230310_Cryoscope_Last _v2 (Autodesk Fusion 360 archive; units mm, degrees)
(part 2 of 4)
sketch "Sketch16" plane through (0, 0, 41) normal (0, 0, 1) x axis (-1, 0, 0)
  line L1 (27, 60.2629) -> (27, -27)
  line L2 (-95.627, 60.2629) -> (27, 60.2629)
  line L3 (-95.627, -27) -> (-95.627, 60.2629)
  line L4 (27, -27) -> (-95.627, -27)
  line L5 (-39.0584, 3.6943) -> (-95.627, 60.2629)
  line L6 (-15.627, 60.2629) -> (-95.627, 60.2629)
  line L7 (-46.8335, 11.4694) -> (-43.298, 7.9338)
  line L8 (-50.369, 15.0049) -> (-46.8335, 11.4694)
  line L9 (-53.9046, 18.5404) -> (-50.369, 15.0049)
  line L10 (-57.4401, 22.076) -> (-53.9046, 18.5404)
  line L11 (-60.9756, 25.6115) -> (-57.4401, 22.076)
  line L12 (-64.5112, 29.147) -> (-60.9756, 25.6115)
  line L13 (-68.0467, 32.6826) -> (-64.5112, 29.147)
  line L14 (-71.5822, 36.2181) -> (-68.0467, 32.6826)
  line L15 (-75.1178, 39.7536) -> (-71.5822, 36.2181)
  line L16 (-78.6533, 43.2892) -> (-75.1178, 39.7536)
  line L17 (-82.1888, 46.8247) -> (-78.6533, 43.2892)
  line L18 (-58.7209, 0.9961) -> (-36.3603, 23.3568)
  line L19 (-34.9461, 21.9426) -> (-57.3067, -0.4181)
  line L20 (-58.0138, 0.289) -> (-35.6532, 22.6497)
  line L21 (-66.0761, 0.712) -> (-36.0761, 30.712)
  line L22 (-34.6619, 29.2978) -> (-64.6619, -0.7022)
  line L23
  line L24 (-71.9322, 1.927) -> (-37.2912, 36.5681)
  line L25 (-35.877, 35.1538) -> (-70.518, 0.5128)
  line L26 (-71.2251, 1.2199) -> (-36.5841, 35.861)
  line L27 (-76.8555, 4.0748) -> (-39.4389, 41.4914)
  line L28 (-38.0247, 40.0772) -> (-75.4413, 2.6606)
  line L29 (-76.1484, 3.3677) -> (-38.7318, 40.7843)
  line L30 (-81.0477, 6.9537) -> (-42.3178, 45.6835)
  line L31 (-40.9036, 44.2693) -> (-79.6334, 5.5395)
  line L32 (-80.3406, 6.2466) -> (-41.6107, 44.9764)
  line L33 (-84.5832, 10.4892) -> (-45.8534, 49.2191)
  line L34 (-44.4391, 47.8049) -> (-83.169, 9.075)
  line L35 (-83.8761, 9.7821) -> (-45.1463, 48.512)
  line L36 (-87.4621, 14.6814) -> (-50.0455, 52.098)
  line L37 (-48.6313, 50.6838) -> (-86.0479, 13.2672)
  line L38 (-86.755, 13.9743) -> (-49.3384, 51.3909)
  line L39 (-89.6099, 19.6047) -> (-54.9688, 54.2457)
  line L40 (-53.5546, 52.8315) -> (-88.1956, 18.1905)
  line L41 (-88.9027, 18.8976) -> (-54.2617, 53.5386)
  line L42 (-90.8249, 25.4608) -> (-60.8249, 55.4608)
  line L43 (-59.4107, 54.0465) -> (-89.4107, 24.0465)
  line L44 (-90.1178, 24.7536) -> (-60.1178, 54.7536)
  line L45 (-90.5408, 32.8159) -> (-68.1801, 55.1766)
  line L46 (-66.7659, 53.7624) -> (-89.1265, 31.4017)
  line L47 (-89.8336, 32.1088) -> (-67.473, 54.4695)
  line L48 (-49.6809, 2.9651) -> (-38.3292, 14.3168)
  line L49 (-36.915, 12.9026) -> (-48.2667, 1.5509)
  line L50 (-48.9738, 2.258) -> (-37.6221, 13.6097)
  line L51 (-89.3384, 41.0894) -> (-76.4535, 53.9743)
  line L52 (-75.0393, 52.5601) -> (-87.9242, 39.6752)
  line L53 (-88.6313, 40.3823) -> (-75.7464, 53.2672)
  arc A1 centre (-58.0138, 0.289) radius 1 clockwise from (-57.3067, -0.4181) to (-58.7209, 0.9961)
  arc A2 centre (-35.6532, 22.6497) radius 1 clockwise from (-36.3603, 23.3568) to (-34.9461, 21.9426)
  arc A3 centre (-65.369, 0.0049) radius 1 clockwise from (-64.6619, -0.7022) to (-66.0761, 0.712)
  arc A4 centre (-35.369, 30.0049) radius 1 clockwise from (-35.369, 30.0049) to (-36.0761, 30.712)
  arc A5 centre (-71.2251, 1.2199) radius 1 clockwise from (-70.518, 0.5128) to (-71.9322, 1.927)
  arc A6 centre (-36.5841, 35.861) radius 1 clockwise from (-37.2912, 36.5681) to (-35.877, 35.1538)
  arc A7 centre (-76.1484, 3.3677) radius 1 clockwise from (-75.4413, 2.6606) to (-76.8555, 4.0748)
  arc A8 centre (-38.7318, 40.7843) radius 1 clockwise from (-39.4389, 41.4914) to (-38.0247, 40.0772)
  arc A9 centre (-80.3406, 6.2466) radius 1 clockwise from (-79.6334, 5.5395) to (-81.0477, 6.9537)
  arc A10 centre (-41.6107, 44.9764) radius 1 clockwise from (-42.3178, 45.6835) to (-40.9036, 44.2693)
  arc A11 centre (-83.8761, 9.7821) radius 1 clockwise from (-83.169, 9.075) to (-84.5832, 10.4892)
  arc A12 centre (-45.1463, 48.512) radius 1 clockwise from (-45.8534, 49.2191) to (-44.4391, 47.8049)
  arc A13 centre (-86.755, 13.9743) radius 1 clockwise from (-86.0479, 13.2672) to (-87.4621, 14.6814)
  arc A14 centre (-49.3384, 51.3909) radius 1 clockwise from (-50.0455, 52.098) to (-48.6313, 50.6838)
  arc A15 centre (-88.9027, 18.8976) radius 1 clockwise from (-88.1956, 18.1905) to (-89.6099, 19.6047)
  arc A16 centre (-54.2617, 53.5386) radius 1 clockwise from (-54.9688, 54.2457) to (-53.5546, 52.8315)
  arc A17 centre (-90.1178, 24.7536) radius 1 clockwise from (-89.4107, 24.0465) to (-90.8249, 25.4608)
  arc A18 centre (-60.1178, 54.7536) radius 1 clockwise from (-60.8249, 55.4608) to (-59.4107, 54.0465)
  arc A19 centre (-89.8336, 32.1088) radius 1 clockwise from (-89.1265, 31.4017) to (-90.5408, 32.8159)
  arc A20 centre (-67.473, 54.4695) radius 1 clockwise from (-68.1801, 55.1766) to (-66.7659, 53.7624)
  arc A21 centre (-62.7434, 27.3793) radius 27.5 clockwise from (-58.0138, 0.289) to (-64.0494, -0.0897)
  arc A22 centre (-62.7434, 27.3793) radius 27.5 clockwise from (-65.369, 0.0049) to (-70.1385, 0.8923)
  arc A23 centre (-62.7434, 27.3793) radius 27.5 clockwise from (-71.2251, 1.2199) to (-75.2262, 2.8756)
  arc A24 centre (-62.7434, 27.3793) radius 27.5 clockwise from (-76.1484, 3.3677) to (-79.5558, 5.6171)
  arc A25 centre (-62.7434, 27.3793) radius 27.5 clockwise from (-80.3406, 6.2466) to (-83.8761, 9.7821)
  arc A26 centre (-62.7434, 27.3793) radius 27.5 clockwise from (-84.5056, 10.5668) to (-86.755, 13.9743)
  arc A27 centre (-62.7434, 27.3793) radius 27.5 clockwise from (-87.2471, 14.8964) to (-88.9027, 18.8976)
  arc A28 centre (-62.7434, 27.3793) radius 27.5 clockwise from (-89.2304, 19.9841) to (-90.1178, 24.7536)
  arc A29 centre (-62.7434, 27.3793) radius 27.5 clockwise from (-90.2124, 26.0733) to (-89.8336, 32.1088)
  arc A30 centre (-62.7434, 27.3793) radius 27.5 clockwise from (-89.4599, 33.8968) to (-69.2609, 54.0958)
  arc A31 centre (-62.7434, 27.3793) radius 27.5 clockwise from (-67.473, 54.4695) to (-60.1178, 54.7536)
  arc A32 centre (-62.7434, 27.3793) radius 27.5 clockwise from (-59.1242, 54.6401) to (-54.2617, 53.5386)
  arc A33 centre (-62.7434, 27.3793) radius 27.5 clockwise from (-53.3162, 53.213) to (-49.3384, 51.3909)
  arc A34 centre (-62.7434, 27.3793) radius 27.5 clockwise from (-48.4743, 50.8876) to (-45.931, 49.1415)
  arc A35 centre (-62.7434, 27.3793) radius 27.5 clockwise from (-45.1463, 48.512) to (-41.6107, 44.9764)
  arc A36 centre (-62.7434, 27.3793) radius 27.5 clockwise from (-40.9812, 44.1917) to (-38.7318, 40.7843)
  arc A37 centre (-62.7434, 27.3793) radius 27.5 clockwise from (-38.2398, 39.8621) to (-36.5841, 35.861)
  arc A38 centre (-62.7434, 27.3793) radius 27.5 clockwise from (-36.2564, 34.7744) to (-35.369, 30.0049)
  arc A39 centre (-62.7434, 27.3793) radius 27.5 clockwise from (-36.0269, 20.8618) to (-56.2259, 0.6628)
  arc A40 centre (-62.7434, 27.3793) radius 27.5 clockwise from (-35.2744, 28.6853) to (-35.6532, 22.6497)
  circle C1 centre (-62.7434, 27.3793) radius 27.5
  arc A41 centre (-48.9738, 2.258) radius 1 clockwise from (-48.2667, 1.5509) to (-49.6809, 2.9651)
  arc A42 centre (-37.6221, 13.6097) radius 1 clockwise from (-38.3292, 14.3168) to (-36.915, 12.9026)
  arc A43 centre (-88.6313, 40.3823) radius 1 clockwise from (-87.9242, 39.6752) to (-89.3384, 41.0894)
  arc A44 centre (-75.7464, 53.2672) radius 1 clockwise from (-76.4535, 53.9743) to (-75.0393, 52.5601)
  point P4 (-95.627, 60.2629)
  point P6 (-95.627, 60.2629)
  point P9 (-62.7434, 27.3793)
  point P10 (-43.298, 7.9338)
  point P19 (-75.1178, 39.7536)
  point P21 (-82.1888, 46.8247)
  point P11 (-46.8335, 11.4694)
  point P28 (-46.8335, 11.4694)
  point P12 (-50.369, 15.0049)
  point P35 (-50.369, 15.0049)
  point P13 (-53.9046, 18.5404)
  point P42 (-53.9046, 18.5404)
  point P14 (-57.4401, 22.076)
  point P49 (-57.4401, 22.076)
  point P15 (-60.9756, 25.6115)
  point P56 (-60.9756, 25.6115)
  point P62 (-83.8761, 9.7821)
  point P16 (-64.5112, 29.147)
  point P63 (-64.5112, 29.147)
  point P69 (-86.755, 13.9743)
  point P17 (-68.0467, 32.6826)
  point P70 (-68.0467, 32.6826)
  point P76 (-88.9027, 18.8976)
  point P18 (-71.5822, 36.2181)
  point P77 (-71.5822, 36.2181)
  point P83 (-90.1178, 24.7536)
  point P84 (-75.1178, 39.7536)
  point P90 (-89.8336, 32.1088)
  point P20 (-78.6533, 43.2892)
  point P91 (-78.6533, 43.2892)
  point P92 (-56.2259, 0.6628)
  point P93 (-64.0494, -0.0897)
  point P95 (-70.1385, 0.8923)
  point P97 (-75.2262, 2.8756)
  point P99 (-79.5558, 5.6171)
  point P101 (-84.5056, 10.5668)
  point P103 (-87.2471, 14.8964)
  point P105 (-89.2304, 19.9841)
  point P107 (-90.2124, 26.0733)
  point P109 (-89.4599, 33.8968)
  point P111 (-69.2609, 54.0958)
  point P113 (-59.1242, 54.6401)
  point P115 (-53.3162, 53.213)
  point P117 (-48.4743, 50.8876)
  point P119 (-45.931, 49.1415)
  point P121 (-40.9812, 44.1917)
  point P123 (-38.2398, 39.8621)
  point P125 (-36.2564, 34.7744)
  point P127 (-35.2744, 28.6853)
  point P129 (-36.0269, 20.8618)
  point P138 (-43.298, 7.9338)
  point P145 (-82.1888, 46.8247)
  point P7 (-39.0584, 3.6943)
  horizontal L6
  coincident P4 P6
  coincident L5 P9
  coincident P10 A39
  coincident L5 P10
  parallel L5 L7
  parallel L5 L8
  parallel L5 L9
  parallel L5 L10
  parallel L5 L11
  parallel L5 L12
  parallel L5 L13
  parallel L5 L14
  coincident L5 P19
  parallel L5 L16
  coincident L5 P21
  tangent L18 A1
  tangent A1 L19
  parallel L18 L19
  tangent L19 A2
  tangent L18 A2
  perpendicular L5 L20
  coincident P11 P28
  midpoint L20 P28
  tangent L21 A3
  tangent A3 L22
  parallel L21 L22
  tangent L22 A4
  tangent L21 A4
  perpendicular L9 L23
  coincident P12 P35
  midpoint L23 P35
  tangent L24 A5
  tangent A5 L25
  parallel L24 L25
  tangent L25 A6
  tangent L24 A6
  perpendicular L9 L26
  coincident P13 P42
  midpoint L26 P42
  tangent L27 A7
  tangent A7 L28
  parallel L27 L28
  tangent L28 A8
  tangent L27 A8
  perpendicular L5 L29
  coincident P14 P49
  midpoint L29 P49
  tangent L30 A9
  tangent A9 L31
  parallel L30 L31
  tangent L31 A10
  tangent L30 A10
  perpendicular L12 L32
  coincident P15 P56
  midpoint L32 P56
  tangent L33 A11
  tangent A11 L34
  parallel L33 L34
  tangent L34 A12
  tangent L33 A12
  coincident P62 A39
  perpendicular L5 L35
  coincident P16 P63
  midpoint L35 P63
  tangent L36 A13
  tangent A13 L37
  parallel L36 L37
  tangent L37 A14
  tangent L36 A14
  coincident P69 A39
  perpendicular L13 L38
  coincident P17 P70
  midpoint L38 P70
  tangent L39 A15
  tangent A15 L40
  parallel L39 L40
  tangent L40 A16
  tangent L39 A16
  coincident P76 A39
  perpendicular L5 L41
  coincident P18 P77
  midpoint L41 P77
  tangent L42 A17
  tangent A17 L43
  parallel L42 L43
  tangent L43 A18
  tangent L42 A18
  coincident P83 A39
  perpendicular L15 L44
  coincident P19 P84
  midpoint L44 P84
  tangent L45 A19
  tangent A19 L46
  parallel L45 L46
  tangent L46 A20
  tangent L45 A20
  coincident P90 A39
  perpendicular L17 L47
  coincident P20 P91
  midpoint L47 P91
  coincident L19 P92
  coincident L22 P93
  concentric A21 A39
  coincident L25 P95
  concentric A22 A39
  coincident L28 P97
  concentric A23 A39
  coincident L31 P99
  concentric A24 A39
  coincident L33 P101
  concentric A25 A39
  coincident L36 P103
  concentric A26 A39
  coincident L39 P105
  concentric A27 A39
  coincident L42 P107
  concentric A28 A39
  coincident L45 P109
  concentric A29 A39
  coincident L45 P111
  concentric A30 A39
  coincident A18 P113
  concentric A31 A39
  coincident A16 P115
  concentric A32 A39
  coincident A14 P117
  concentric A33 A39
  coincident L33 P119
  concentric A34 A39
  coincident L31 P121
  concentric A35 A39
  coincident L28 P123
  concentric A36 A39
  coincident L25 P125
  concentric A37 A39
  coincident L22 P127
  concentric A38 A39
  coincident L19 P129
  concentric A39 A40
  concentric A23 C1
  tangent L48 A41
  tangent A41 L49
  parallel L48 L49
  tangent L49 A42
  tangent L48 A42
  perpendicular L7 L50
  coincident P10 P138
  midpoint L50 P138
  tangent L51 A43
  tangent A43 L52
  parallel L51 L52
  tangent L52 A44
  tangent L51 A44
  perpendicular L17 L53
  coincident P21 P145
  midpoint L53 P145
  dimension "d95" angle L5 L6 = 45
  dimension "d96" distance P6 P7 = 80
  dimension "d97" diameter A39 = 55
  dimension "d98" distance P10 P11 = 5
  dimension "d99" distance P11 P12 = 5
  dimension "d100" distance P12 P13 = 5
  dimension "d101" distance P13 P14 = 5
  dimension "d102" distance P14 P15 = 5
  dimension "d103" distance P15 P16 = 5
  dimension "d104" distance P16 P17 = 5
  dimension "d105" distance P17 P18 = 5
  dimension "d106" distance P18 P19 = 5
  dimension "d107" distance P19 P20 = 5
  dimension "d108" distance P20 P21 = 5
  dimension "d109" diameter A1 = 2
  dimension "d110" diameter A3 = 2
  dimension "d111" diameter A5 = 2
  dimension "d112" diameter A7 = 2
  dimension "d113" diameter A9 = 2
  dimension "d114" diameter A11 = 2
  dimension "d115" diameter A13 = 2
  dimension "d116" diameter A15 = 2
  dimension "d117" diameter A17 = 2
  dimension "d118" diameter A19 = 2
  dimension "d137" diameter A41 = 2
  dimension "d138" diameter A43 = 2
extrude "Extrude15" cut sketch "Sketch16" profile of L5 L7 L8 L9 L10 L11 L12 L13 L14 L15 L16 L17 L18 A1 L19 A2 L21 A3 L22 A4 L24 A5 L25 A6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 against normal blind 4
sketch "Sketch17" plane through (0, 0, 41) normal (0, 0, 1) x axis (-1, 0, 0)
  line L1 (-54.9688, 54.2457) -> (-89.6099, 19.6047)
  line L2 (-88.1956, 18.1905) -> (-53.5546, 52.8315)
  line L3 (-39.4389, 41.4914) -> (-76.8555, 4.0748)
  line L4 (-75.4413, 2.6606) -> (-38.0247, 40.0772)
  line L5 (-36.3603, 23.3568) -> (-58.7209, 0.9961)
  line L6 (-57.3067, -0.4181) -> (-34.9461, 21.9426)
  line L7 (-42.3178, 45.6835) -> (-81.0477, 6.9537)
  line L8 (-79.6334, 5.5395) -> (-40.9036, 44.2693)
  line L9 (-60.8249, 55.4608) -> (-90.8249, 25.4608)
  line L10 (-89.4107, 24.0465) -> (-59.4107, 54.0465)
  line L11 (-50.0455, 52.098) -> (-87.4621, 14.6814)
  line L12 (-86.0479, 13.2672) -> (-48.6313, 50.6838)
  line L13 (-37.2912, 36.5681) -> (-71.9322, 1.927)
  line L14 (-70.518, 0.5128) -> (-35.877, 35.1538)
  line L15 (-36.0761, 30.712) -> (-66.0761, 0.712)
  line L16 (-64.6619, -0.7022) -> (-34.6619, 29.2978)
  line L17 (-45.8534, 49.2191) -> (-84.5832, 10.4892)
  line L18 (-83.169, 9.075) -> (-44.4391, 47.8049)
  line L19 (-68.1801, 55.1766) -> (-90.5408, 32.8159)
  line L20 (-89.1265, 31.4017) -> (-66.7659, 53.7624)
  line L21 (27, 60.2629) -> (27, -27)
  line L22 (-95.627, 60.2629) -> (27, 60.2629)
  line L23 (-95.627, -27) -> (-95.627, 60.2629)
  line L24 (27, -27) -> (-95.627, -27)
  arc A1 centre (-54.2617, 53.5386) radius 1 clockwise from (-54.9688, 54.2457) to (-53.5546, 52.8315)
  arc A2 centre (-88.9027, 18.8976) radius 1 clockwise from (-88.1956, 18.1905) to (-89.6099, 19.6047)
  arc A3 centre (-38.7318, 40.7843) radius 1 clockwise from (-39.4389, 41.4914) to (-38.0247, 40.0772)
  arc A4 centre (-76.1484, 3.3677) radius 1 clockwise from (-75.4413, 2.6606) to (-76.8555, 4.0748)
  arc A5 centre (-35.6532, 22.6497) radius 1 clockwise from (-36.3603, 23.3568) to (-34.9461, 21.9426)
  arc A6 centre (-58.0138, 0.289) radius 1 clockwise from (-57.3067, -0.4181) to (-58.7209, 0.9961)
  arc A7 centre (-41.6107, 44.9764) radius 1 clockwise from (-42.3178, 45.6835) to (-40.9036, 44.2693)
  arc A8 centre (-80.3406, 6.2466) radius 1 clockwise from (-79.6334, 5.5395) to (-81.0477, 6.9537)
  arc A9 centre (-60.1178, 54.7536) radius 1 clockwise from (-60.8249, 55.4608) to (-59.4107, 54.0465)
  arc A10 centre (-90.1178, 24.7536) radius 1 clockwise from (-89.4107, 24.0465) to (-90.8249, 25.4608)
  arc A11 centre (-49.3384, 51.3909) radius 1 clockwise from (-50.0455, 52.098) to (-48.6313, 50.6838)
  arc A12 centre (-86.755, 13.9743) radius 1 clockwise from (-86.0479, 13.2672) to (-87.4621, 14.6814)
  arc A13 centre (-36.5841, 35.861) radius 1 clockwise from (-37.2912, 36.5681) to (-35.877, 35.1538)
  arc A14 centre (-71.2251, 1.2199) radius 1 clockwise from (-70.518, 0.5128) to (-71.9322, 1.927)
  arc A15 centre (-35.369, 30.0049) radius 1 clockwise from (-35.369, 30.0049) to (-36.0761, 30.712)
  arc A16 centre (-65.369, 0.0049) radius 1 clockwise from (-64.6619, -0.7022) to (-66.0761, 0.712)
  arc A17 centre (-45.1463, 48.512) radius 1 clockwise from (-45.8534, 49.2191) to (-44.4391, 47.8049)
  arc A18 centre (-83.8761, 9.7821) radius 1 clockwise from (-83.169, 9.075) to (-84.5832, 10.4892)
  arc A19 centre (-67.473, 54.4695) radius 1 clockwise from (-68.1801, 55.1766) to (-66.7659, 53.7624)
  arc A20 centre (-89.8336, 32.1088) radius 1 clockwise from (-89.1265, 31.4017) to (-90.5408, 32.8159)
sketch "Sketch18" plane through (0, 0, -4) normal (0, 0, -1) x axis (1, 0, 0)
  line L1 (95.627, 63.2629) -> (98.627, 60.2629)
  line L2 (-27, 63.2629) -> (95.627, 63.2629)
  line L3 (-30, 60.2629) -> (-27, 63.2629)
  line L4 (-30, -27) -> (-30, 60.2629)
  line L5 (-27, -30) -> (-30, -27)
  line L6 (95.627, -30) -> (-27, -30)
  line L7 (98.627, -27) -> (95.627, -30)
  line L8 (98.627, 60.2629) -> (98.627, -27)
  line L9 (37.1924, -3.9295) -> (-28.5, 61.7629)
  line L10 (-14.9535, 48.2164) -> (-18.489, 51.7519)
  line L11 (-11.418, 44.6808) -> (-14.9535, 48.2164)
  line L12 (-7.8824, 41.1453) -> (-11.418, 44.6808)
  line L13 (-4.3469, 37.6098) -> (-7.8824, 41.1453)
  line L14 (-0.8114, 34.0742) -> (-4.3469, 37.6098)
  line L15 (-6.3407, 55.415) -> (-22.1521, 39.6036)
  line L16 (-23.5663, 41.0178) -> (-7.7549, 56.8292)
  line L17 (-7.0478, 56.1221) -> (-22.8592, 40.3107)
  line L18 (-0.7109, 53.9737) -> (-20.7109, 33.9737)
  line L19 (-22.1251, 35.388) -> (-2.1251, 55.388)
  line L20 (-1.418, 54.6808) -> (-21.418, 34.6808)
  line L21 (3.4313, 51.0448) -> (-17.7819, 29.8316)
  line L22 (-19.1962, 31.2458) -> (2.017, 52.459)
  line L23 (2.7242, 51.7519) -> (-18.489, 30.5387)
  line L24 (6.3602, 46.9027) -> (-13.6398, 26.9027)
  line L25 (-15.054, 28.3169) -> (4.946, 48.3169)
  line L26 (5.6531, 47.6098) -> (-14.3469, 27.6098)
  line L27 (7.8014, 41.2728) -> (-8.01, 25.4614)
  line L28 (-9.4242, 26.8757) -> (6.3872, 42.687)
  line L29 (7.0943, 41.9799) -> (-8.7171, 26.1686)
  line L30 (-17.0748, 53.1661) -> (-19.9033, 50.3377)
  line L31 (6.2597, 32.66) -> (0.6028, 27.0032)
  line L32 (-0.8114, 28.4174) -> (4.8455, 34.0742)
  line L33 (5.5526, 33.3671) -> (-0.1043, 27.7103)
  line L34 (-14.9535, 53.8732) -> (-20.6104, 48.2164)
  line L35 (-22.0246, 49.6306) -> (-16.3677, 55.2875)
  line L36 (-15.6606, 54.5803) -> (-21.3175, 48.9235)
  circle C1 centre (66.2, 17.5) radius 3
  circle C2 centre (14, 50.8) radius 3
  circle C3 centre (66.2, 45.5) radius 3
  circle C4 centre (15, 2.5) radius 3
  circle C5 centre (-7.8824, 41.1453) radius 15
  arc A1 centre (-7.0478, 56.1221) radius 1 clockwise from (-7.7549, 56.8292) to (-6.3407, 55.415)
  arc A2 centre (-22.8592, 40.3107) radius 1 clockwise from (-22.1521, 39.6036) to (-23.5663, 41.0178)
  arc A3 centre (-1.418, 54.6808) radius 1 clockwise from (-2.1251, 55.388) to (-0.7109, 53.9737)
  arc A4 centre (-21.418, 34.6808) radius 1 clockwise from (-20.7109, 33.9737) to (-22.1251, 35.388)
  arc A5 centre (2.7242, 51.7519) radius 1 clockwise from (2.017, 52.459) to (3.4313, 51.0448)
  arc A6 centre (-18.489, 30.5387) radius 1 clockwise from (-17.7819, 29.8316) to (-19.1962, 31.2458)
  arc A7 centre (5.6531, 47.6098) radius 1 clockwise from (4.946, 48.3169) to (6.3602, 46.9027)
  arc A8 centre (-14.3469, 27.6098) radius 1 clockwise from (-13.6398, 26.9027) to (-15.054, 28.3169)
  arc A9 centre (7.0943, 41.9799) radius 1 clockwise from (6.3872, 42.687) to (7.8014, 41.2728)
  arc A10 centre (-8.7171, 26.1686) radius 1 clockwise from (-8.01, 25.4614) to (-9.4242, 26.8757)
  arc A11 centre (5.5526, 33.3671) radius 1 clockwise from (4.8455, 34.0742) to (6.2597, 32.66)
  arc A12 centre (-0.1043, 27.7103) radius 1 clockwise from (0.6028, 27.0032) to (-0.8114, 28.4174)
  arc A13 centre (-15.6606, 54.5803) radius 1 clockwise from (-16.3677, 55.2875) to (-14.9535, 53.8732)
  arc A14 centre (-21.3175, 48.9235) radius 1 clockwise from (-20.6104, 48.2164) to (-22.0246, 49.6306)
  point P14 (-28.5, 61.7629)
  point P16 (-7.8824, 41.1453)
  point P17 (-18.489, 51.7519)
  point P19 (-11.418, 44.6808)
  point P28 (-7.0478, 56.1221)
  point P18 (-14.9535, 48.2164)
  point P29 (-14.9535, 48.2164)
  point P35 (-1.418, 54.6808)
  point P36 (-11.418, 44.6808)
  point P42 (2.7242, 51.7519)
  point P43 (-7.8824, 41.1453)
  point P49 (5.6531, 47.6098)
  point P21 (-4.3469, 37.6098)
  point P50 (-4.3469, 37.6098)
  point P56 (7.0943, 41.9799)
  point P22 (-0.8114, 34.0742)
  point P57 (-0.8114, 34.0742)
  point P60 (-18.489, 51.7519)
  point P67 (2.7242, 30.5387)
  point P74 (-18.489, 51.7519)
  point P20 (-7.8824, 41.1453)
  midpoint L3 P14
  perpendicular L3 L9
  coincident L9 P16
  coincident C5 P17
  coincident L9 P17
  perpendicular L3 L10
  coincident L9 P19
  parallel L9 L12
  parallel L9 L13
  parallel L9 L14
  tangent L15 A1
  tangent A1 L16
  parallel L15 L16
  tangent L16 A2
  tangent L15 A2
  coincident C5 P28
  perpendicular L11 L17
  coincident P18 P29
  midpoint L17 P29
  tangent L18 A3
  tangent A3 L19
  parallel L18 L19
  tangent L19 A4
  tangent L18 A4
  coincident C5 P35
  perpendicular L11 L20
  coincident P19 P36
  midpoint L20 P36
  tangent L21 A5
  tangent A5 L22
  parallel L21 L22
  tangent L22 A6
  tangent L21 A6
  coincident C5 P42
  perpendicular L13 L23
  coincident P16 P43
  midpoint L23 P43
  tangent L24 A7
  tangent A7 L25
  parallel L24 L25
  tangent L25 A8
  tangent L24 A8
  coincident C5 P49
  perpendicular L14 L26
  coincident P21 P50
  midpoint L26 P50
  tangent L27 A9
  tangent A9 L28
  parallel L27 L28
  tangent L28 A10
  tangent L27 A10
  coincident C5 P56
  perpendicular L14 L29
  coincident P22 P57
  midpoint L29 P57
  perpendicular L9 L30
  coincident P17 P60
  midpoint L30 P60
  tangent L31 A11
  tangent A11 L32
  parallel L31 L32
  tangent L32 A12
  tangent L31 A12
  perpendicular L9 L33
  coincident L9 P67
  coincident C5 P67
  midpoint L33 P67
  tangent L34 A13
  tangent A13 L35
  parallel L34 L35
  tangent L35 A14
  tangent L34 A14
  perpendicular L10 L36
  coincident P60 P74
  midpoint L36 P74
  dimension "d121" diameter C5 = 30
  dimension "d122" distance P17 P18 = 5
  dimension "d123" distance P18 P19 = 5
  dimension "d124" distance P19 P20 = 5
  dimension "d125" distance P20 P21 = 5
  dimension "d126" distance P21 P22 = 5
  dimension "d127" diameter A1 = 2
  dimension "d128" diameter A3 = 2
  dimension "d129" diameter A5 = 2
  dimension "d130" diameter A7 = 2
  dimension "d131" diameter A9 = 2
  dimension "d133" diameter A11 = 2
  dimension "d134" diameter A13 = 2
extrude "Extrude16" cut sketch "Sketch18" profile of L9 C5 L10 L11 L12 L13 L14 L15 A1 L16 A2 L18 A3 L19 A4 L21 L22 L24 A7 L25 A8 L27 A9 L28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 against normal blind 3
extrude "Extrude17" add sketch "Sketch16" profile of A40 A1 L19 A3 L22 A5 L25 A7 L28 A9 L31 L33 A11 L36 A13 L39 A15 L42 A17 L45 A19 C1 against normal blind 3
extrude "Extrude18" cut sketch "Sketch16" profile of L5 A40 L7 L17 C1 L48 L52 against normal blind 3
extrude "Extrude19" add sketch "Sketch16" profile of A40 L19 A2 L22 A4 L25 A6 L28 A8 L31 A10 L33 A12 L36 A14 L39 A16 L42 A18 L45 A20 C1 against normal blind 3
delete_face "DeleteFace8"
delete_face "DeleteFace9"
delete_face "DeleteFace10"
delete_face "DeleteFace11"
delete_face "DeleteFace12"
delete_face "DeleteFace13"
delete_face "DeleteFace14"
delete_face "DeleteFace15"
delete_face "DeleteFace16"
sketch "Sketch19" plane through (0, 0, -4) normal (0, 0, -1) x axis (1, 0, 0)
  line L1 (95.627, 63.2629) -> (98.627, 60.2629)
  line L2 (-27, 63.2629) -> (95.627, 63.2629)
  line L3 (-30, 60.2629) -> (-27, 63.2629)
  line L4 (-30, -27) -> (-30, 60.2629)
  line L5 (-27, -30) -> (-30, -27)
  line L6 (95.627, -30) -> (-27, -30)
  line L7 (98.627, -27) -> (95.627, -30)
  line L8 (98.627, 60.2629) -> (98.627, -27)
  line L9 (-21.4289, 54.6918) -> (-28.5, 61.7629)
  line L10 (90.0559, 54.6918) -> (97.127, 61.7629)
  line L11 (90.0559, -21.4289) -> (97.127, -28.5)
  line L12 (-21.4289, -21.4289) -> (-28.5, -28.5)
  circle C1 centre (66.2, 17.5) radius 3
  circle C2 centre (14, 50.8) radius 3
  circle C3 centre (66.2, 45.5) radius 3
  circle C4 centre (15, 2.5) radius 3
  circle C5 centre (-21.4289, 54.6918) radius 4
  circle C6 centre (90.0559, 54.6918) radius 4
  circle C7 centre (90.0559, -21.4289) radius 4
  circle C8 centre (-21.4289, -21.4289) radius 4
  point P14 (-28.5, 61.7629)
  point P16 (97.127, 61.7629)
  point P18 (97.127, -28.5)
  point P20 (-28.5, -28.5)
  point P15 (-21.4289, 54.6918)
  point P22 (-21.4289, 54.6918)
  point P17 (90.0559, 54.6918)
  point P23 (90.0559, 54.6918)
  point P19 (90.0559, -21.4289)
  point P24 (90.0559, -21.4289)
  point P21 (-21.4289, -21.4289)
  point P25 (-21.4289, -21.4289)
  midpoint L3 P14
  perpendicular L3 L9
  midpoint L1 P16
  perpendicular L1 L10
  midpoint L7 P18
  perpendicular L7 L11
  midpoint L5 P20
  perpendicular L5 L12
  coincident P15 P22
  coincident P17 P23
  coincident P19 P24
  coincident P21 P25
  dimension "d145" distance P14 P15 = 10
  dimension "d146" distance P16 P17 = 10
  dimension "d147" distance P18 P19 = 10
  dimension "d148" distance P20 P21 = 10
  dimension "d149" diameter C5 = 8
  dimension "d150" diameter C6 = 8
  dimension "d151" diameter C7 = 8
  dimension "d152" diameter C8 = 8
extrude "Extrude20" add sketch "Sketch19" profile of C5 C6 C7 C8 along normal blind 4
fillet "Fillet1" radius 4
split "Split1"
sketch "Sketch20" plane through (0, 0, 0) normal (0, 0, 1) x axis (1, 0, 0)
  line L1 (115.9553, -70) -> (-40, -70)
  line L2 (115.9553, 32.6455) -> (115.9553, -70)
  line L3 (-40, 32.6455) -> (115.9553, 32.6455)
  line L4 (-40, -70) -> (-40, 32.6455)
  horizontal L1
  vertical L2
  horizontal L3
  vertical L4
extrude "Extrude21" new body sketch "Sketch20" along normal blind 5
move "Move4"
combine "Combine1"
combine "Combine2"
combine "Combine3"
combine "Combine4"
combine "Combine5"
move "Move5"
extrude "Extrude22" cut of existing geometry blind 10.4
sketch "Sketch21" plane through (0, 0, -4) normal (0, 0, -1) x axis (1, 0, 0)
  line L1 (95.627, 63.2629) -> (98.627, 60.2629)
  line L2 (-27, 63.2629) -> (95.627, 63.2629)
  line L3 (-30, 60.2629) -> (-27, 63.2629)
  line L4 (-30, -27) -> (-30, 60.2629)
  line L5 (-27, -30) -> (-30, -27)
  line L6 (95.627, -30) -> (-27, -30)
  line L7 (98.627, -27) -> (95.627, -30)
  line L8 (98.627, 60.2629) -> (98.627, -27)
  line L9 (-6, 5) -> (-6, 50)
  line L10 (-4, 50) -> (-4, 5)
  line L11 (-5, 5) -> (-5, 50)
  circle C1 centre (90.0559, -21.4289) radius 4
  circle C2 centre (-21.4289, -21.4289) radius 4
  circle C3 centre (-21.4289, 54.6918) radius 4
  circle C4 centre (90.0559, 54.6918) radius 4
  circle C5 centre (66.2, 17.5) radius 3
  circle C6 centre (14, 50.8) radius 3
  circle C7 centre (66.2, 45.5) radius 3
  circle C8 centre (15, 2.5) radius 3
  arc A1 centre (-5, 5) radius 1 clockwise from (-4, 5) to (-6, 5)
  arc A2 centre (-5, 50) radius 1 clockwise from (-6, 50) to (-4, 50)
  tangent L9 A1
  tangent A1 L10
  parallel L9 L10
  tangent L10 A2
  tangent L9 A2
  vertical L11
  dimension "d161" diameter A1 = 2
extrude "Extrude23" cut sketch "Sketch21" profile of L9 A1 L10 A2 against normal blind 5
chamfer "Chamfer11" distance 0.6
move "Move6"
sketch "Sketch22" plane through (-30, 0, 0) normal (-1, 0, 0) x axis (0, -1, 0)
  line L1 (60.2629, 38) -> (60.2629, -4)
  line L2 (-27, 38) -> (60.2629, 38)
  line L3 (-27, -4) -> (-27, 38)
  line L4 (60.2629, -4) -> (-27, -4)
  line L5 (33.2629, -4) -> (60.2629, -4)
  line L6 (33.2629, 4) -> (33.2629, -4)
  line L7 (45.2629, 4) -> (33.2629, 4)
  line L8 (45.2629, 15.6) -> (45.2629, 4)
  line L9 (33.2629, 15.6) -> (45.2629, 15.6)
  line L10 (33.2629, 4) -> (33.2629, 15.6)
  line L11 (28.2629, 4) -> (33.2629, 4)
  line L12 (28.2629, 15.6) -> (28.2629, 4)
  line L13 (33.2629, 15.6) -> (28.2629, 15.6)
  line L14 (33.2629, 4) -> (33.2629, 15.6)
  point P2 (60.2629, -4)
  point P6 (60.2629, -4)
  point P7 (33.2629, -4)
  point P8 (33.2629, 4)
  point P9 (45.2629, 4)
  point P11 (33.2629, 15.6)
  point P12 (28.2629, 4)
  coincident P2 P6
  perpendicular L1 L5
  perpendicular L5 L6
  horizontal L7
  vertical L8
  horizontal L9
  vertical L10
  horizontal L11
  vertical L12
  horizontal L13
  vertical L14
  dimension "d165" distance P6 P7 = 27
  dimension "d166" distance P7 P8 = 8
  dimension "d167" distance P8 P9 = 12
  dimension "d168" distance P8 P11 = 11.6
  dimension "d169" distance P8 P12 = 5
extrude "Extrude24" cut sketch "Sketch22" profile of L7 L8 L9 L10 L11 L12 L13 L14 against normal blind 10
sketch "Sketch23" plane through (-27, 0, 0) normal (1, 0, 0) x axis (0, 1, 0)
  line L1 (-45.2629, 15.6) -> (-45.2629, 4)
  line L2 (-28.2629, 15.6) -> (-45.2629, 15.6)
  line L3 (-28.2629, 4) -> (-28.2629, 15.6)
  line L4 (-45.2629, 4) -> (-28.2629, 4)
  line L5 (-52.2629, -2) -> (-52.2629, 38)
  line L6 (19, -2) -> (-52.2629, -2)
  line L7 (19, 38) -> (19, -2)
  line L8 (-52.2629, 38) -> (19, 38)
  line L9 (-28.2629, 4) -> (-45.2629, 15.6)
  line L10 (-45.2629, 4) -> (-28.2629, 15.6)
  line L11 (-25.2629, 18.6) -> (-48.2629, 18.6)
  line L12 (-25.2629, 1) -> (-25.2629, 18.6)
  line L13 (-48.2629, 1) -> (-25.2629, 1)
  line L14 (-48.2629, 18.6) -> (-48.2629, 1)
  line L15 (-25.2629, 1) -> (-48.2629, 18.6)
  line L16 (-48.2629, 1) -> (-25.2629, 18.6)
  point P3 (-45.2629, 15.6)
  point P10 (-45.2629, 15.6)
  point P5 (-28.2629, 4)
  point P11 (-28.2629, 4)
  point P4 (-28.2629, 15.6)
  point P12 (-28.2629, 15.6)
  point P2 (-45.2629, 4)
  point P13 (-45.2629, 4)
  point P18 (-36.7629, 9.8)
  point P16 (-25.2629, 1)
  point P17 (-48.2629, 1)
  point P15 (-25.2629, 18.6)
  coincident P3 P10
  coincident P5 P11
  coincident P4 P12
  coincident P2 P13
  horizontal L11
  perpendicular L11 L12
  parallel L11 L13
  parallel L12 L14
  coincident L15 P18
  coincident L16 P18
  midpoint L10 P18
  dimension "d172" distance P16 P17 = 23 (= "17 mm + 6 mm")
  dimension "d173" distance P15 P16 = 17.6 (= "11.600 mm + 6 mm")
extrude "Extrude25" add sketch "Sketch23" profile of L1 L2 L3 L4 L11 L12 L13 L14 along normal blind 5
extrude "Extrude26" add of existing geometry blind 3
offset_faces "OffsetFaces3" distance -0.15
offset_faces "OffsetFaces4" distance -0.25
component_from_bodies "Body->Comp3"
component_from_bodies "Body->Comp4"
component_from_bodies "Body->Comp5"
base_feature "Base Feature1"
sketch "Sketch1" plane through (0, 0, -2) normal (0, 0, 1) x axis (-1, 0, 0)
  line L1 (22, 25.2629) -> (27, 25.2629)
  line L2 (22, 48.2629) -> (22, 25.2629)
  line L3 (27, 48.2629) -> (22, 48.2629)
  line L4 (27, 52.2629) -> (27, 48.2629)
  line L5 (19, 60.2629) -> (27, 52.2629)
  line L6 (-87.627, 60.2629) -> (19, 60.2629)
  line L7 (-95.627, 52.2629) -> (-87.627, 60.2629)
  line L8 (-95.627, -19) -> (-95.627, 52.2629)
  line L9 (-87.627, -27) -> (-95.627, -19)
  line L10 (19, -27) -> (-87.627, -27)
  line L11 (27, -19) -> (19, -27)
  line L12 (27, 25.2629) -> (27, -19)
  line L13 (6, 5) -> (6, 50)
  line L14 (4, 50) -> (4, 5)
  line L15 (-76.8267, -5) -> (10, -5)
  line L16 (-76.8267, 58.4411) -> (-76.8267, -5)
  line L17 (10, 58.4411) -> (-76.8267, 58.4411)
  line L18 (10, -5) -> (10, 58.4411)
  circle C1 centre (-14, 50.8) radius 5
  circle C2 centre (-66.2, 17.5) radius 5
  circle C3 centre (-15, 2.5) radius 5
  circle C4 centre (-66.2, 45.5) radius 5
  arc A1 centre (5, 5) radius 1 clockwise from (6, 5) to (4, 5)
  arc A2 centre (5, 50) radius 1 clockwise from (4, 50) to (6, 50)
  horizontal L15
  vertical L16
  horizontal L17
  vertical L18
split "Split1"
move "Move1"
sketch "Sketch2" plane through (0, 0, -2) normal (0, 0, 1) x axis (-1, 0, 0)
  line L1 (10, -5) -> (10, 58.4411)
  line L2 (-76.8267, -5) -> (10, -5)
  line L3 (-76.8267, 58.4411) -> (-76.8267, -5)
  line L4 (10, 58.4411) -> (-76.8267, 58.4411)
  line L5 (22, 25.2629) -> (27, 25.2629)
  line L6 (22, 48.2629) -> (22, 25.2629)
  line L7 (27, 48.2629) -> (22, 48.2629)
  line L8 (27, 52.2629) -> (27, 48.2629)
  line L9 (19, 60.2629) -> (27, 52.2629)
  line L10 (-87.627, 60.2629) -> (19, 60.2629)
  line L11 (-95.627, 52.2629) -> (-87.627, 60.2629)
  line L12 (-95.627, -19) -> (-95.627, 52.2629)
  line L13 (-87.627, -27) -> (-95.627, -19)
  line L14 (19, -27) -> (-87.627, -27)
  line L15 (27, -19) -> (19, -27)
  line L16 (27, 25.2629) -> (27, -19)
combine "Combine1"
sketch "Sketch3" plane through (0, 0, -2) normal (0, 0, 1) x axis (-1, 0, 0)
extrude "Extrude1" add of existing geometry blind 20 named "d1_1"
extrude "Extrude2" add of existing geometry blind 3 named "d3_1"
offset_faces "OffsetFaces1" distance -0.05 named "d5_1"
sketch "Sketch4" plane through (0, 0, 0) normal (0, 0, 1) x axis (-1, 0, 0)
  circle C1 centre (-34, 47.8) radius 1.5
  circle C2 centre (-34, 47.8) radius 5
  circle C3 centre (-34, 47.8) radius 2.5
  concentric C1 C3
  dimension "d6_1" diameter C3 = 5
sketch "Sketch5" plane through (0, 0, 0) normal (0, 0, 1) x axis (-1, 0, 0)
  circle C1 centre (-35, -0.5) radius 1.5
  circle C2 centre (-35, -0.5) radius 5
  circle C3 centre (-35, -0.5) radius 2.5
  concentric C1 C3
  dimension "d7_1" diameter C3 = 5
sketch "Sketch6" plane through (0, 0, 0) normal (0, 0, 1) x axis (-1, 0, 0)
  circle C1 centre (-86.2, 42.5) radius 1.5
  circle C2 centre (-86.2, 42.5) radius 5
  circle C3 centre (-86.2, 42.5) radius 2.5
  concentric C1 C3
  dimension "d8_1" diameter C3 = 5
sketch "Sketch7" plane through (0, 0, 0) normal (0, 0, 1) x axis (-1, 0, 0)
  circle C1 centre (-86.2, 14.5) radius 1.5
  circle C2 centre (-86.2, 14.5) radius 5
  circle C3 centre (-86.2, 14.5) radius 2.5
  concentric C1 C3
  dimension "d9_1" diameter C3 = 5
extrude "Extrude3" cut blind -2 named "d10_1"
extrude "Extrude4" cut of existing geometry blind -10 named "d12_1"
sketch "Sketch8" plane through (0, 0, -2) normal (0, 0, 1) x axis (-1, 0, 0)
  line L1 (-95.627, 52.2629) -> (-87.627, 60.2629)
  line L2 (-95.627, -19) -> (-95.627, 52.2629)
  line L3 (-87.627, -27) -> (-95.627, -19)
  line L4 (19, -27) -> (-87.627, -27)
  line L5 (27, -19) -> (19, -27)
  line L6 (27, 25.2629) -> (27, -19)
  line L7 (22, 25.2629) -> (27, 25.2629)
  line L8 (22, 48.2629) -> (22, 25.2629)
  line L9 (27, 48.2629) -> (22, 48.2629)
  line L10 (27, 52.2629) -> (27, 48.2629)
  line L11 (19, 60.2629) -> (27, 52.2629)
  line L12 (-87.627, 60.2629) -> (19, 60.2629)
  line L13 (-14, 2) -> (-14, 47)
  line L14 (-16, 47) -> (-16, 2)
  circle C1 centre (-35, -0.5) radius 3
  circle C2 centre (-86.2, 14.5) radius 2.5
  circle C3 centre (-86.2, 42.5) radius 2.5
  circle C4 centre (-34, 47.8) radius 3
  arc A1 centre (-15, 2) radius 1 clockwise from (-14, 2) to (-16, 2)
  arc A2 centre (-15, 47) radius 1 clockwise from (-16, 47) to (-14, 47)
  circle C5 centre (-35, -0.5) radius 3
  circle C6 centre (-34, 47.8) radius 3
  circle C7 centre (-35, -0.5) radius 1.5
  circle C8 centre (-34, 47.8) radius 1.5
  concentric C1 C5
  concentric C4 C6
  concentric C5 C7
  concentric C6 C8
  dimension "d14_1" diameter C7 = 3
  dimension "d15_1" diameter C8 = 3
extrude "Extrude5" add sketch "Sketch8" profile of C1 C4 C5 C6 C7 C8 against normal blind 1 named "d16_1"
sketch "Sketch9" plane through (0, 0, -3.6) normal (0, 0, -1) x axis (1, 0, 0)
  line L1 (93.9851, 55.4411) -> (86.1267, 55.4411)
  arc A1 centre (90.0559, 54.6918) radius 4 clockwise from (86.1267, 55.4411) to (93.9851, 55.4411)
  circle C1 centre (90.0559, 54.6918) radius 4
  concentric A1 C1
extrude "Extrude6" cut sketch "Sketch9" profile of L1 C1 along normal blind 0.4 named "d18_1"
sketch "Sketch10" plane through (0, 0, -4) normal (0, 0, -1) x axis (1, 0, 0)
  line L1 (14, 47) -> (14, 2)
  line L2 (16, 2) -> (16, 47)
  line L3 (95.627, 63.2629) -> (98.627, 60.2629)
  line L4 (-27, 63.2629) -> (95.627, 63.2629)
  line L5 (-30, 60.2629) -> (-27, 63.2629)
  line L6 (-30, -27) -> (-30, 60.2629)
  line L7 (-27, -30) -> (-30, -27)
  line L8 (95.627, -30) -> (-27, -30)
  line L9 (98.627, -27) -> (95.627, -30)
  line L10 (98.627, 60.2629) -> (98.627, -27)
  circle C1 centre (90.0559, 54.6918) radius 4
  circle C2 centre (35, -0.5) radius 3
  circle C3 centre (34, 47.8) radius 3
  arc A1 centre (15, 47) radius 1 clockwise from (14, 47) to (16, 47)
  arc A2 centre (15, 2) radius 1 clockwise from (16, 2) to (14, 2)
  circle C4 centre (90.0559, -21.4289) radius 4
  circle C5 centre (-21.4289, -21.4289) radius 4
  circle C6 centre (-21.4289, 54.6918) radius 4
  circle C7 centre (86.2, 14.5) radius 1.5
  circle C8 centre (86.2, 42.5) radius 1.5
  circle C9 centre (86.2, 14.5) radius 3
  circle C10 centre (86.2, 42.5) radius 3
  concentric C7 C9
  concentric C8 C10
  dimension "d20_1" diameter C9 = 6
  dimension "d21_1" diameter C10 = 6
extrude "Extrude7" cut sketch "Sketch10" profile of C7 C8 C9 C10 against normal blind 1 named "d22_1"
extrude "Extrude8" add of existing geometry blind 1 named "d24_1"
extrude "Extrude9" add of existing geometry blind 1 named "d26_1"
offset_faces "OffsetFaces2" distance -0.1 named "d28_1"
offset_faces "OffsetFaces3" distance -0.2 named "d29_1"
sketch "Sketch11" plane through (0, 0, -2) normal (0, 0, 1) x axis (-1, 0, 0)
  line L1 (-95.627, 52.2629) -> (-87.627, 60.2629)
  line L2 (-95.627, -19) -> (-95.627, 52.2629)
  line L3 (-87.627, -27) -> (-95.627, -19)
  line L4 (19, -27) -> (-87.627, -27)
  line L5 (27, -19) -> (19, -27)
  line L6 (27, 25.2629) -> (27, -19)
  line L7 (22, 25.2629) -> (27, 25.2629)
  line L8 (22, 48.2629) -> (22, 25.2629)
  line L9 (27, 48.2629) -> (22, 48.2629)
  line L10 (27, 52.2629) -> (27, 48.2629)
  line L11 (19, 60.2629) -> (27, 52.2629)
  line L12 (-87.627, 60.2629) -> (19, 60.2629)
  line L13 (-14, 2) -> (-14, 47)
  line L14 (-16, 47) -> (-16, 2)
  circle C1 centre (-35, -0.5) radius 2.5
  circle C2 centre (-34, 47.8) radius 2.5
  circle C3 centre (-86.2, 14.5) radius 2.5
  circle C4 centre (-86.2, 42.5) radius 2.5
  arc A1 centre (-15, 2) radius 1 clockwise from (-14, 2) to (-16, 2)
  arc A2 centre (-15, 47) radius 1 clockwise from (-16, 47) to (-14, 47)
sketch "Sketch12" plane through (0, 30, 0) normal (0, 1, 0) x axis (-1, 0, 0)
  line L1 (27, 38) -> (27, -5)
  line L2 (-95.627, 38) -> (27, 38)
  line L3 (-95.627, -5) -> (-95.627, 38)
  line L4 (27, -5) -> (-95.627, -5)
  line L5 (4, 25.3923) -> (-56, 25.3923)
  line L6 (10, 15) -> (4, 25.3923)
  line L7 (-50, 15) -> (10, 15)
  line L8 (-56, 30.242) -> (-51.8, 27.8172)
  line L9 (-60.2, 27.8172) -> (-56, 30.242)
  line L10 (-60.2, 22.9674) -> (-60.2, 27.8172)
  line L11 (-56, 20.5426) -> (-60.2, 22.9674)
  line L12 (-51.8, 22.9674) -> (-56, 20.5426)
  line L13 (-51.8, 27.8172) -> (-51.8, 22.9674)
  line L14 (-44, 30.242) -> (-39.8, 27.8172)
  line L15 (-48.2, 27.8172) -> (-44, 30.242)
  line L16 (-48.2, 22.9674) -> (-48.2, 27.8172)
  line L17 (-44, 20.5426) -> (-48.2, 22.9674)
  line L18 (-39.8, 22.9674) -> (-44, 20.5426)
  line L19 (-39.8, 27.8172) -> (-39.8, 22.9674)
  line L20 (-32, 20.5426) -> (-36.2, 22.9674)
  line L21 (-27.8, 22.9674) -> (-32, 20.5426)
  line L22 (-27.8, 27.8172) -> (-27.8, 22.9674)
  line L23 (-32, 30.242) -> (-27.8, 27.8172)
  line L24 (-36.2, 27.8172) -> (-32, 30.242)
  line L25 (-36.2, 22.9674) -> (-36.2, 27.8172)
  line L26 (-8, 30.242) -> (-3.8, 27.8172)
  line L27 (-12.2, 27.8172) -> (-8, 30.242)
  line L28 (-12.2, 22.9674) -> (-12.2, 27.8172)
  line L29 (-8, 20.5426) -> (-12.2, 22.9674)
  line L30 (-3.8, 22.9674) -> (-8, 20.5426)
  line L31 (-3.8, 27.8172) -> (-3.8, 22.9674)
  line L32 (4, 20.5426) -> (-0.2, 22.9674)
  line L33 (8.2, 22.9674) -> (4, 20.5426)
  line L34 (8.2, 27.8172) -> (8.2, 22.9674)
  line L35 (4, 30.242) -> (8.2, 27.8172)
  line L36 (-0.2, 27.8172) -> (4, 30.242)
  line L37 (-0.2, 22.9674) -> (-0.2, 27.8172)
  line L38 (10, 10.1503) -> (5.8, 12.5751)
  line L39 (14.2, 12.5751) -> (10, 10.1503)
  line L40 (14.2, 17.4249) -> (14.2, 12.5751)
  line L41 (10, 19.8497) -> (14.2, 17.4249)
  line L42 (5.8, 17.4249) -> (10, 19.8497)
  line L43 (5.8, 12.5751) -> (5.8, 17.4249)
  line L44 (-2, 19.8497) -> (2.2, 17.4249)
  line L45 (-6.2, 17.4249) -> (-2, 19.8497)
  line L46 (-6.2, 12.5751) -> (-6.2, 17.4249)
  line L47 (-2, 10.1503) -> (-6.2, 12.5751)
  line L48 (2.2, 12.5751) -> (-2, 10.1503)
  line L49 (2.2, 17.4249) -> (2.2, 12.5751)
  line L50 (-26, 10.1503) -> (-30.2, 12.5751)
  line L51 (-21.8, 12.5751) -> (-26, 10.1503)
  line L52 (-21.8, 17.4249) -> (-21.8, 12.5751)
  line L53 (-26, 19.8497) -> (-21.8, 17.4249)
  line L54 (-30.2, 17.4249) -> (-26, 19.8497)
  line L55 (-30.2, 12.5751) -> (-30.2, 17.4249)
  line L56 (-38, 19.8497) -> (-33.8, 17.4249)
  line L57 (-42.2, 17.4249) -> (-38, 19.8497)
  line L58 (-42.2, 12.5751) -> (-42.2, 17.4249)
  line L59 (-38, 10.1503) -> (-42.2, 12.5751)
  line L60 (-33.8, 12.5751) -> (-38, 10.1503)
  line L61 (-33.8, 17.4249) -> (-33.8, 12.5751)
  line L62 (-50, 19.8497) -> (-45.8, 17.4249)
  line L63 (-54.2, 17.4249) -> (-50, 19.8497)
  line L64 (-54.2, 12.5751) -> (-54.2, 17.4249)
  line L65 (-50, 10.1503) -> (-54.2, 12.5751)
  line L66 (-45.8, 12.5751) -> (-50, 10.1503)
  line L67 (-45.8, 17.4249) -> (-45.8, 12.5751)
  circle C1 centre (10, 15) radius 3.35
  circle C2 centre (-8, 25.3923) radius 3.35
  circle C3 centre (-2, 15) radius 3.35
  circle C4 centre (4, 25.3923) radius 3.35
  circle C5 centre (-56, 25.3923) radius 3.35
  circle C6 centre (-32, 25.3923) radius 3.35
  circle C7 centre (-26, 15) radius 3.35
  circle C8 centre (-50, 15) radius 3.35
  circle C9 centre (-44, 25.3923) radius 3.35
  circle C10 centre (-38, 15) radius 3.35
  circle C11 centre (-81.627, 15) radius 3.2
  circle C12 centre (-81.627, 25.3923) radius 3.2
  point P6 (-56, 25.3923)
  point P18 (-56, 25.3923)
  point P5 (4, 25.3923)
  point P19 (4, 25.3923)
  point P2 (10, 15)
  point P20 (10, 15)
  point P9 (-50, 15)
  point P21 (-50, 15)
  point P28 (-56, 25.3923)
  point P10 (-44, 25.3923)
  point P35 (-44, 25.3923)
  point P7 (-32, 25.3923)
  point P42 (-32, 25.3923)
  point P3 (-8, 25.3923)
  point P49 (-8, 25.3923)
  point P56 (4, 25.3923)
  point P63 (10, 15)
  point P4 (-2, 15)
  point P70 (-2, 15)
  point P8 (-26, 15)
  point P77 (-26, 15)
  point P11 (-38, 15)
  point P84 (-38, 15)
  point P91 (-50, 15)
  coincident P6 P18
  coincident P5 P19
  coincident P2 P20
  coincident P9 P21
  coincident P18 P28
  coincident P10 P35
  coincident P7 P42
  coincident P3 P49
  coincident P19 P56
  coincident P20 P63
  coincident P4 P70
  coincident P8 P77
  coincident P11 P84
  coincident P21 P91
  dimension "d30_1" distance P28 L13 = 4.2
  dimension "d31_1" distance P35 L19 = 4.2
  dimension "d32_1" distance P42 L25 = 4.2
  dimension "d33_1" distance P49 L31 = 4.2
  dimension "d34_1" distance P56 L37 = 4.2
  dimension "d35_1" distance P63 L43 = 4.2
  dimension "d36_1" distance P70 L49 = 4.2
  dimension "d37_1" distance P77 L55 = 4.2
  dimension "d38_1" distance P84 L61 = 4.2
  dimension "d39_1" distance P91 L67 = 4.2
extrude "Extrude10" cut sketch "Sketch12" profile of C1 C2 C3 C4 C5 C6 C7 C8 C9 C10 L5 L6 L7 L8 L9 L10 L11 L12 L13 L14 L15 L16 L17 L18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 against normal blind 1 named "d40_1"
sketch "Sketch13" plane through (0, 27, 0) normal (0, -1, 0) x axis (1, 0, 0)
  line L1 (87.627, 38) -> (87.627, -2)
  line L2 (-19, 38) -> (87.627, 38)
  line L3 (-19, -2) -> (-19, 38)
  line L4 (87.627, -2) -> (-19, -2)
  line L5 (-10, 9.15) -> (-10, 11.65)
  line L6 (-15.85, 15) -> (-13.35, 15)
  line L7 (-15.85, 15) -> (-13.35, 15)
  line L8 (-15.85, 9.15) -> (-15.85, 15)
  line L9 (-10, 9.15) -> (-15.85, 9.15)
  line L10 (-10, 11.65) -> (-10, 9.15)
  line L11 (61.85, 25.3923) -> (59.35, 25.3923)
  line L12 (56, 31.2423) -> (61.85, 31.2423)
  line L13 (56, 28.7423) -> (56, 31.2423)
  line L14 (-15.85, 31.2423) -> (61.85, 31.2423)
  line L15 (-15.85, 9.15) -> (-15.85, 31.2423)
  line L16 (61.85, 9.15) -> (-15.85, 9.15)
  line L17 (61.85, 31.2423) -> (61.85, 9.15)
  circle C1 centre (-10, 15) radius 3.35
  circle C2 centre (8, 25.3923) radius 3.35
  circle C3 centre (2, 15) radius 3.35
  circle C4 centre (-4, 25.3923) radius 3.35
  circle C5 centre (56, 25.3923) radius 3.35
  circle C6 centre (32, 25.3923) radius 3.35
  circle C7 centre (26, 15) radius 3.35
  circle C8 centre (50, 15) radius 3.35
  circle C9 centre (44, 25.3923) radius 3.35
  circle C10 centre (38, 15) radius 3.35
  circle C11 centre (81.627, 15) radius 2
  circle C12 centre (81.627, 25.3923) radius 2
  point P28 (-13.35, 15)
  point P29 (-10, 11.65)
  point P30 (59.35, 25.3923)
  point P31 (56, 28.7423)
  point P6 (-10, 15)
  point P20 (-15.85, 15)
  point P10 (56, 25.3923)
  point P23 (61.85, 25.3923)
  point P25 (56, 31.2423)
  perpendicular L4 L5
  perpendicular L5 L6
  horizontal L7
  vertical L8
  horizontal L9
  vertical L10
  horizontal L11
  horizontal L12
  vertical L13
  horizontal L14
  vertical L15
  horizontal L16
  vertical L17
  coincident C1 P28
  coincident C1 P29
  coincident C5 P30
  coincident C5 P31
  dimension "d44_1" distance P6 P20 = 5.85
  dimension "d45_1" distance P10 P23 = 5.85
  dimension "d46_1" distance P10 P25 = 5.85
extrude "Extrude11" new body sketch "Sketch13" profile of C1 C2 C3 C4 C5 C6 C7 C8 C9 C10 L5 L6 L7 L8 L9 L10 L11 L12 L13 L14 L15 L16 L17 along normal blind 1 named "d47_1"
extrude "Extrude12" cut of existing geometry blind -1 named "d49_1"
component_insert "Component Insert3"
component_insert "Component Insert4"
component_insert "Component Insert5"
component_insert "Component Insert6"
component_insert "Component Insert7"
component_insert "Component Insert8"
component_insert "Component Insert9"
component_insert "Component Insert10"
component_insert "Component Insert11"
component_insert "Component Insert12"
component_insert "Component Insert13"
component_insert "Component Insert14"
component_insert "Component Insert15"
position "Position1"
extrude "Extrude27" new body of existing geometry blind 0.01
component_insert "Component Insert16"
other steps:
base_feature "Base Feature1"
base_feature "Base Feature1"
base_feature "Base Feature1"
create_component "CreateComponent3"
remove_body "RemoveBody3"
create_component "CreateComponent4"
remove_body "RemoveBody4"
create_component "CreateComponent5"
remove_body "RemoveBody5"
create_component "CreateComponent6"

design "CP33_M-Step"
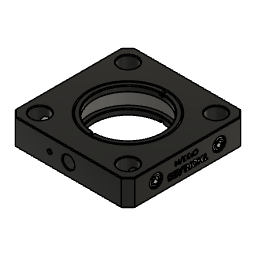
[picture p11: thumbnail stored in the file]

design "LED_combiner_mount"
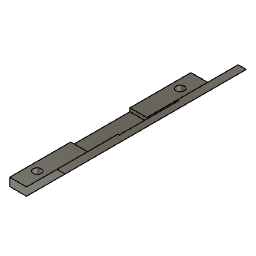
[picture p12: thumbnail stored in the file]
sketch "Sketch1" plane through (0, 0, 0) normal (0, 0, 1) x axis (1, 0, 0)
  line L1 (24, 0) -> (0, 0)
  line L2 (24, 32) -> (24, 0)
  line L3 (0, 32) -> (24, 32)
  line L4 (0, 0) -> (0, 32)
  point P1 (0, 0)
  point P2 (0, 0)
  point P3 (24, 0)
  point P5 (0, 32)
  horizontal L1
  vertical L2
  horizontal L3
  vertical L4
  coincident P1 P2
  dimension "d1" distance P2 P3 = 24
  dimension "d2" distance P2 P5 = 32
extrude "Extrude1" new body sketch "Sketch1" along normal blind 1
sketch "Sketch2" plane through (0, 0, 1) normal (0, 0, 1) x axis (-1, 0, 0)
  line L1 (0, 0) -> (0, -32)
  line L2 (-24, 0) -> (0, 0)
  line L3 (-24, -32) -> (-24, 0)
  line L4 (0, -32) -> (-24, -32)
  line L5 (-24, 0) -> (0, -32)
  line L6 (-24, -32) -> (0, 0)
  line L7 (-24, 0) -> (0, 0)
  line L8 (-24, -32) -> (-24, 0)
  line L9 (0, -32) -> (-24, -32)
  line L10 (0, 0) -> (0, -32)
  line L11 (-24, -32) -> (0, 0)
  line L12 (0, -32) -> (-24, 0)
  line L13 (-28, 31.5) -> (4, 31.5)
  line L14 (-28, -63.5) -> (-28, 31.5)
  line L15 (4, -63.5) -> (-28, -63.5)
  line L16 (4, 31.5) -> (4, -63.5)
  line L17 (-28, -63.5) -> (4, 31.5)
  line L18 (4, -63.5) -> (-28, 31.5)
  point P2 (0, -32)
  point P6 (0, -32)
  point P4 (-24, 0)
  point P7 (-24, 0)
  point P3 (0, 0)
  point P8 (0, 0)
  point P5 (-24, -32)
  point P9 (-24, -32)
  point P13 (-12, -16)
  point P18 (-12, -16)
  point P16 (-28, -63.5)
  point P17 (4, -63.5)
  point P15 (-28, 31.5)
  coincident P2 P6
  coincident P4 P7
  coincident P3 P8
  coincident P5 P9
  horizontal L7
  perpendicular L7 L8
  parallel L7 L9
  parallel L8 L10
  coincident L11 P13
  coincident L12 P13
  midpoint L6 P13
  horizontal L13
  perpendicular L13 L14
  parallel L13 L15
  parallel L14 L16
  coincident L17 P18
  coincident L18 P18
  coincident P13 P18
  dimension "d5" distance P16 P17 = 32
  dimension "d6" distance P15 P16 = 95
extrude "Extrude2" add sketch "Sketch2" profile of L1 L2 L3 L4 L5 L6 L7 L8 L9 L10 L13 L14 L15 L16 along normal blind 3
extrude "Extrude3" cut of existing geometry blind -1
sketch "Sketch3" plane through (0, 0, 1) normal (0, 0, -1) x axis (1, 0, 0)
  line L1 (-4, -63.5) -> (-4, 31.5)
  line L2 (28, -63.5) -> (-4, -63.5)
  line L3 (28, 31.5) -> (28, -63.5)
  line L4 (-4, 31.5) -> (28, 31.5)
  line L5 (23.5, -31.5) -> (0.5, -31.5)
  line L6 (23.5, -0.5) -> (23.5, -31.5)
  line L7 (0.5, -0.5) -> (23.5, -0.5)
  line L8 (0.5, -31.5) -> (0.5, -0.5)
  line L9 (6.7789, -0.5) -> (-4, 31.5)
  line L10 (28, -63.5) -> (17.2211, -31.5)
  line L11 (6.7789, -31.5) -> (-4, -63.5)
  line L12 (28, 31.5) -> (17.2211, -0.5)
  point P2 (-4, 31.5)
  point P6 (-4, 31.5)
  point P4 (28, -63.5)
  point P7 (28, -63.5)
  point P3 (-4, -63.5)
  point P8 (-4, -63.5)
  point P5 (28, 31.5)
  point P9 (28, 31.5)
  point P14 (6.7789, -0.5)
  point P15 (17.2211, -0.5)
  point P16 (17.2211, -31.5)
  point P17 (6.7789, -31.5)
  point P12 (23.5, -0.5)
  point P13 (0.5, -0.5)
  point P11 (23.5, -31.5)
  coincident P2 P6
  coincident P4 P7
  coincident P3 P8
  coincident P5 P9
  horizontal L5
  perpendicular L5 L6
  parallel L5 L7
  parallel L6 L8
  coincident L7 P14
  collinear L9 L10
  coincident L7 P15
  collinear L11 L12
  coincident L5 P16
  coincident L5 P17
  dimension "d11" distance P12 P13 = 23
  dimension "d12" distance P11 P12 = 31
